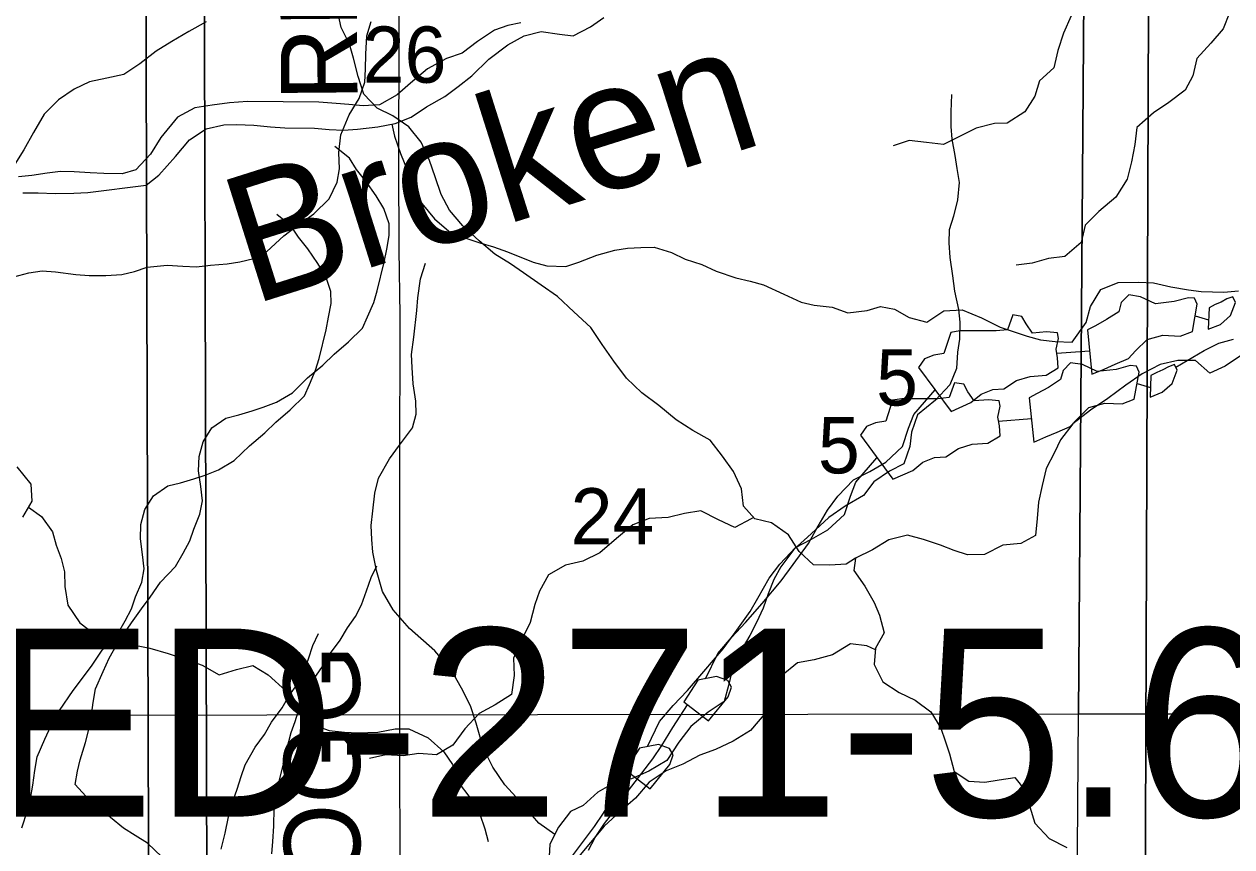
# Model space of a CAD drawing. Extents: x -21.1 to 50.3, y 0 to 22.1.
# Drawn here: x 3.669 to 4.567, y 18.044 to 18.656 of the extents above; entities that cross this region are included whole.
import ezdxf

# ---------------------------------------------------------------- set-up
doc = ezdxf.new("R2010")
doc.units = 0
for name, color, linetype in [('GM_X_Minor_Lake', 7, 'Continuous'), ('GM_X_Minor_River', 7, 'Continuous'), ('GM_X_Minor_River_Text', 7, 'Continuous'), ('GM_X_Section', 7, 'Continuous'), ('GM_X_Section_Text', 7, 'Continuous'), ('GM_X_Township_Road', 7, 'Continuous'), ('GM_X_Township_Road_Text', 7, 'Continuous'), ('SH_Data', 7, 'Continuous')]:
    doc.layers.add(name, color=color, linetype=linetype)

msp = doc.modelspace()

# ---------------------------------------------------------------- linework, layer by layer
at = {"layer": 'GM_X_Minor_Lake'}
for points in [[(4.46292, 18.3955), (4.47198, 18.39939), (4.48028, 18.4029), (4.49009, 18.40718), (4.49534, 18.41293), (4.50397, 18.42137), (4.51569, 18.42453), (4.52859, 18.42391), (4.53765, 18.42742), (4.54122, 18.44757), (4.53927, 18.4521), (4.53472, 18.45243), (4.52413, 18.44966), (4.51012, 18.44799), (4.49906, 18.45319), (4.49032, 18.45461), (4.4847, 18.44886), (4.48288, 18.44201), (4.47384, 18.43622), (4.46555, 18.43158), (4.45952, 18.42848)], [(4.54939, 18.42906), (4.55845, 18.43257), (4.56596, 18.43911), (4.56965, 18.44901), (4.5677, 18.45316), (4.56317, 18.4516), (4.55902, 18.44927), (4.55449, 18.44733), (4.54997, 18.445)], [(4.54997, 18.445), (4.54939, 18.42906)], [(4.35818, 18.36782), (4.3729, 18.37443), (4.38041, 18.38058), (4.3891, 18.38409), (4.39743, 18.38456), (4.40685, 18.39073), (4.41705, 18.39387), (4.4288, 18.39476), (4.43784, 18.40017), (4.43737, 18.40775), (4.43616, 18.41419), (4.43797, 18.42217), (4.43716, 18.42634), (4.42919, 18.42701), (4.41858, 18.42614), (4.41396, 18.43292), (4.41086, 18.43858), (4.40402, 18.43965), (4.39997, 18.4286), (4.39164, 18.42775), (4.36471, 18.42784), (4.3579, 18.42663), (4.35276, 18.41102), (4.34519, 18.4098), (4.3384, 18.40707), (4.33392, 18.40057)], [(4.45952, 18.42848), (4.46292, 18.3955)], [(4.33392, 18.40057), (4.35818, 18.36782)], [(4.41963, 18.34499), (4.42869, 18.34888), (4.43699, 18.35238), (4.44681, 18.35666), (4.45205, 18.36241), (4.46068, 18.37085), (4.4724, 18.37401), (4.4853, 18.37339), (4.49436, 18.3769), (4.49793, 18.39705), (4.49598, 18.40158), (4.49143, 18.40191), (4.48084, 18.39915), (4.46683, 18.39748), (4.45577, 18.40267), (4.44703, 18.40409), (4.44141, 18.39834), (4.43959, 18.39149), (4.43055, 18.3857), (4.42226, 18.38106), (4.41623, 18.37796)], [(4.5061, 18.37855), (4.51516, 18.38206), (4.52267, 18.38859), (4.52636, 18.3985), (4.52441, 18.40265), (4.51988, 18.40108), (4.51573, 18.39876), (4.5112, 18.39681), (4.50668, 18.39449)], [(4.50668, 18.39449), (4.5061, 18.37855)], [(4.31489, 18.3173), (4.32961, 18.32391), (4.33712, 18.33006), (4.34581, 18.33357), (4.35414, 18.33404), (4.36356, 18.34021), (4.37376, 18.34336), (4.38551, 18.34424), (4.39455, 18.34965), (4.39408, 18.35723), (4.39288, 18.36367), (4.39468, 18.37166), (4.39388, 18.37582), (4.3859, 18.3765), (4.37529, 18.37563), (4.37067, 18.3824), (4.36757, 18.38807), (4.36073, 18.38913), (4.35668, 18.37808), (4.34835, 18.37723), (4.32142, 18.37732), (4.31461, 18.37611), (4.30948, 18.3605), (4.30191, 18.35928), (4.29511, 18.35655), (4.29063, 18.35005)], [(4.41623, 18.37796), (4.41963, 18.34499)], [(4.29063, 18.35005), (4.31489, 18.3173)], [(4.17759, 18.13746), (4.19218, 18.15545), (4.19475, 18.16268), (4.19204, 18.16759), (4.18367, 18.17053), (4.16967, 18.16773), (4.15923, 18.15168)], [(4.15923, 18.15168), (4.17759, 18.13746)], [(4.1343, 18.08694), (4.14889, 18.10493), (4.15146, 18.11217), (4.14875, 18.11707), (4.14038, 18.12002), (4.12638, 18.11721), (4.11594, 18.10116)], [(4.11594, 18.10116), (4.1343, 18.08694)]]:
    msp.add_lwpolyline(points, dxfattribs=at)
at = {"layer": 'GM_X_Minor_River'}
for points in [[(3.6677, 18.53063), (3.67909, 18.53052), (3.69161, 18.53001), (3.70566, 18.53025), (3.71591, 18.5309), (3.75924, 18.53616), (3.76881, 18.54366), (3.7811, 18.55759), (3.79148, 18.57002), (3.80409, 18.57825), (3.81702, 18.58116), (3.82652, 18.58144), (3.83942, 18.58094), (3.85193, 18.57967), (3.86255, 18.5788), (3.88457, 18.57858), (3.89557, 18.57771), (3.90619, 18.57722), (3.91645, 18.57788), (3.93165, 18.57962), (3.94458, 18.58215), (3.9564, 18.58697), (3.96786, 18.59445), (3.98161, 18.60229), (3.99156, 18.60978), (4.00151, 18.61766), (4.01416, 18.63007), (4.02831, 18.64056), (4.04053, 18.64727), (4.05309, 18.65057), (4.06674, 18.64853), (4.07697, 18.64728), (4.08995, 18.65399), (4.09989, 18.66111)], [(4.28702, 18.25864), (4.28018, 18.25407), (4.26801, 18.25329), (4.25583, 18.25366), (4.24516, 18.26353), (4.23715, 18.27607), (4.22458, 18.2848), (4.21202, 18.28783), (4.20364, 18.29732), (4.2021, 18.31025), (4.19637, 18.32318), (4.18798, 18.33457), (4.17883, 18.34635), (4.16589, 18.35356), (4.1537, 18.36153), (4.14075, 18.37217), (4.12817, 18.38165), (4.11674, 18.39267), (4.10721, 18.40521), (4.09844, 18.41775), (4.09005, 18.43028), (4.07748, 18.44206), (4.06529, 18.45345), (4.0531, 18.4618), (4.04015, 18.47092), (4.03025, 18.47775), (4.01882, 18.48496), (4.00701, 18.49483), (3.99482, 18.50585), (3.98491, 18.51762), (3.9788, 18.5294), (3.97422, 18.54233), (3.97002, 18.55449), (3.96391, 18.56818), (3.95476, 18.57957), (3.94295, 18.58793), (3.93115, 18.59362), (3.92124, 18.60387), (3.91703, 18.61718), (3.91359, 18.63086), (3.91053, 18.64113), (3.90442, 18.65367), (3.90175, 18.66622)], [(4.44738, 18.66234), (4.4417, 18.6494), (4.43753, 18.63646), (4.4345, 18.62353), (4.42386, 18.61401), (4.42046, 18.6026), (4.41286, 18.5908), (4.39994, 18.58241), (4.39042, 18.58202), (4.37673, 18.57858), (4.3524, 18.56638), (4.33984, 18.56789), (4.3269, 18.56939), (4.31511, 18.56557)], [(4.56534, 18.66439), (4.5604, 18.65259), (4.55129, 18.64193), (4.54103, 18.63051), (4.53801, 18.61757), (4.53232, 18.60692), (4.52015, 18.59778), (4.50875, 18.59016), (4.49621, 18.57911), (4.49471, 18.56656), (4.49244, 18.55363), (4.48903, 18.54069), (4.48068, 18.52737), (4.46814, 18.51671), (4.45788, 18.50643), (4.45486, 18.49349), (4.4427, 18.48321), (4.43052, 18.48167), (4.41835, 18.47824), (4.40656, 18.4767)], [(3.80397, 18.65773), (3.79104, 18.65049), (3.7785, 18.64325), (3.76671, 18.636), (3.75455, 18.62648), (3.74277, 18.61848), (3.73021, 18.6158), (3.71728, 18.61313), (3.70587, 18.60779), (3.69409, 18.59979), (3.68345, 18.58912), (3.67548, 18.57542), (3.66827, 18.56248), (3.6603, 18.54992), (3.64928, 18.53812), (3.63674, 18.52593)], [(3.66081, 18.46789), (3.67218, 18.47092), (3.68204, 18.47244), (3.69189, 18.47168), (3.70705, 18.46979), (3.71691, 18.46903), (3.72942, 18.46903), (3.74117, 18.46979), (3.75065, 18.47207), (3.76013, 18.47511), (3.77491, 18.47662), (3.78666, 18.47587), (3.7969, 18.47549), (3.80713, 18.47663), (3.81964, 18.47777), (3.82912, 18.47929), (3.83935, 18.48156), (3.84921, 18.48687), (3.86173, 18.49863), (3.87121, 18.50584), (3.8841, 18.51494), (3.89548, 18.52595), (3.90155, 18.53846), (3.90307, 18.54832), (3.9027, 18.56046), (3.90422, 18.57373), (3.91029, 18.58853), (3.91788, 18.60067), (3.92206, 18.6128), (3.92244, 18.62266), (3.92283, 18.63366), (3.92359, 18.64732), (3.92663, 18.65794)], [(4.03798, 18.65718), (4.02846, 18.65499), (4.01856, 18.65168), (4.00594, 18.64306), (3.99446, 18.63444), (3.98266, 18.63039), (3.96853, 18.62293), (3.9559, 18.61204), (3.94594, 18.60341), (3.93295, 18.59594), (3.9208, 18.59531), (3.91018, 18.59617), (3.9007, 18.59703), (3.8878, 18.59792), (3.83466, 18.59846), (3.82137, 18.59745), (3.80844, 18.59568), (3.79552, 18.59391), (3.78254, 18.58683), (3.77024, 18.57176), (3.76252, 18.5593), (3.75177, 18.54764), (3.74149, 18.5447), (3.72782, 18.54484), (3.71758, 18.54532), (3.70582, 18.5462), (3.69557, 18.5463), (3.68569, 18.54526), (3.67429, 18.54348), (3.66441, 18.54244)], [(4.35835, 18.60375), (4.35797, 18.59086), (4.35796, 18.57986), (4.35871, 18.57038), (4.36098, 18.55824), (4.36249, 18.54876), (4.364, 18.53814), (4.36286, 18.52524), (4.35982, 18.51311), (4.35678, 18.50287), (4.3564, 18.49338), (4.35715, 18.48239), (4.35904, 18.46873), (4.36055, 18.45736), (4.36358, 18.4437), (4.36471, 18.43422), (4.36432, 18.4217), (4.3628, 18.41184), (4.36204, 18.39971), (4.3571, 18.38757), (4.34648, 18.37619), (4.33321, 18.36519), (4.32865, 18.35229), (4.32751, 18.34167), (4.32295, 18.32878), (4.31234, 18.32347), (4.30058, 18.3155), (4.293, 18.30526), (4.27935, 18.29729), (4.26721, 18.28895), (4.25394, 18.27681), (4.24104, 18.26505), (4.23156, 18.25215), (4.22625, 18.24267), (4.22207, 18.23205), (4.21828, 18.22143), (4.21334, 18.21081), (4.20841, 18.20095), (4.20272, 18.19147), (4.19589, 18.17857), (4.19247, 18.16378), (4.18943, 18.15202), (4.1773, 18.14406), (4.1644, 18.13344), (4.15568, 18.12168), (4.14658, 18.10802), (4.1333, 18.10005), (4.12041, 18.09437), (4.10752, 18.09133), (4.09539, 18.0845), (4.08439, 18.07464), (4.07491, 18.07009), (4.06619, 18.05833), (4.05974, 18.04581), (4.05897, 18.03216)], [(3.94207, 18.58166), (3.9441, 18.57266), (3.94852, 18.5597), (3.95408, 18.54635), (3.95926, 18.53338), (3.96447, 18.52269), (3.97384, 18.5112), (3.98625, 18.50044), (3.99723, 18.49691), (4.00744, 18.49339), (4.01766, 18.49024), (4.02825, 18.48672), (4.04715, 18.47893), (4.05737, 18.47617), (4.07141, 18.47565), (4.08131, 18.47896), (4.09465, 18.48415), (4.10798, 18.48781), (4.11748, 18.48923), (4.12736, 18.48989), (4.13723, 18.49017), (4.15009, 18.48624), (4.16029, 18.4812), (4.17278, 18.47728), (4.18336, 18.47223), (4.19811, 18.46715), (4.20871, 18.46476), (4.21855, 18.462), (4.23367, 18.45501), (4.24651, 18.44918), (4.25636, 18.4468), (4.26963, 18.44553), (4.28135, 18.44123), (4.2958, 18.44298), (4.3057, 18.44592), (4.31592, 18.44392), (4.32687, 18.43773), (4.34012, 18.43418), (4.35274, 18.44279), (4.36641, 18.44341), (4.38077, 18.43757), (4.39474, 18.43059), (4.40496, 18.42706), (4.4148, 18.42393), (4.42464, 18.42117), (4.43563, 18.41992), (4.44815, 18.41941), (4.45856, 18.43412), (4.46171, 18.44586), (4.46944, 18.4587), (4.4824, 18.46389), (4.49758, 18.46411), (4.50859, 18.46362), (4.52146, 18.46045), (4.53473, 18.45842), (4.5442, 18.45718), (4.5609, 18.45663), (4.57192, 18.45766)], [(3.77107, 18.03628), (3.76036, 18.04648), (3.75119, 18.05212), (3.7424, 18.05777), (3.73284, 18.0657), (3.7229, 18.07362), (3.71448, 18.08155), (3.70644, 18.09024), (3.70829, 18.10013), (3.71014, 18.10849), (3.71426, 18.12143), (3.71649, 18.13018), (3.71834, 18.14007), (3.7198, 18.15109), (3.72165, 18.16136), (3.72728, 18.17431), (3.73179, 18.18421), (3.7382, 18.19564), (3.7484, 18.21051), (3.75595, 18.22081), (3.76237, 18.22958), (3.76992, 18.24064), (3.78127, 18.25248), (3.78693, 18.26239), (3.79183, 18.27153), (3.79482, 18.28029), (3.79933, 18.29133), (3.80117, 18.30122), (3.79997, 18.31185), (3.79838, 18.32361), (3.7987, 18.33425), (3.80169, 18.34528), (3.8081, 18.35558), (3.81872, 18.36285), (3.82822, 18.36518), (3.8381, 18.36828), (3.84646, 18.37098), (3.85633, 18.37484), (3.8681, 18.38174), (3.87945, 18.39282), (3.89082, 18.40238), (3.89915, 18.4104), (3.90975, 18.41958), (3.92035, 18.42989), (3.92411, 18.43827), (3.92862, 18.44893), (3.93124, 18.45769), (3.93644, 18.47899), (3.93829, 18.48849), (3.94014, 18.49876), (3.94009, 18.5075), (3.93622, 18.51887), (3.93046, 18.52834), (3.92278, 18.53931), (3.91588, 18.54801), (3.91051, 18.55633), (3.8998, 18.56501)], [(3.66685, 18.05798), (3.67097, 18.07092), (3.6732, 18.07967), (3.67505, 18.08955), (3.67651, 18.10058), (3.67836, 18.11084), (3.68399, 18.12379), (3.68851, 18.13369), (3.69491, 18.14513), (3.70511, 18.16), (3.71266, 18.17029), (3.71908, 18.17907), (3.72663, 18.19013), (3.73799, 18.20197), (3.74364, 18.21187), (3.74854, 18.22102), (3.75153, 18.22977), (3.75604, 18.24081), (3.75788, 18.2507), (3.75668, 18.26133), (3.7551, 18.2731), (3.75542, 18.28373), (3.7584, 18.29477), (3.76481, 18.30506), (3.77543, 18.31233), (3.78493, 18.31467), (3.79481, 18.31776), (3.80317, 18.32047), (3.81304, 18.32432), (3.82481, 18.33122), (3.83616, 18.3423), (3.84753, 18.35186), (3.85586, 18.35989), (3.86646, 18.36906), (3.87706, 18.37938), (3.88082, 18.38775), (3.88533, 18.39842), (3.88795, 18.40717), (3.89315, 18.42847), (3.895, 18.43798), (3.89685, 18.44824), (3.8968, 18.45698), (3.89293, 18.46836), (3.88717, 18.47782), (3.87949, 18.48879), (3.87259, 18.49749), (3.86722, 18.50582), (3.85651, 18.5145)], [(4.06342, 18.05295), (4.05141, 18.06136), (4.03739, 18.07767), (4.02603, 18.0898), (4.01731, 18.10308), (4.01239, 18.11294), (4.00785, 18.12545), (4.00482, 18.13569), (4.00066, 18.14859), (3.99384, 18.16186), (3.98627, 18.17551), (3.97415, 18.18954), (3.9552, 18.20623), (3.94308, 18.22026), (3.93513, 18.23391), (3.93058, 18.24946), (3.92794, 18.26312), (3.92719, 18.2726), (3.92681, 18.28284), (3.92796, 18.29384), (3.92948, 18.30711), (3.93214, 18.31811), (3.94048, 18.33252), (3.94769, 18.34276), (3.95755, 18.35566), (3.96021, 18.3659), (3.95984, 18.37538), (3.95795, 18.38828), (3.9572, 18.40042), (3.95683, 18.41028), (3.95835, 18.42317), (3.96063, 18.44289), (3.96139, 18.45238), (3.9633, 18.46641), (3.96709, 18.47817)], [(4.53971, 18.43907), (4.54965, 18.4361)], [(4.5253, 18.40075), (4.54629, 18.41313), (4.55723, 18.41856), (4.56819, 18.42171)], [(4.57408, 18.4096), (4.56191, 18.4016), (4.5505, 18.39626), (4.53984, 18.40575), (4.5269, 18.40574), (4.51359, 18.40267), (4.50028, 18.39581), (4.48812, 18.38743), (4.47482, 18.37753), (4.46189, 18.36877), (4.44859, 18.35848), (4.43947, 18.34668), (4.43492, 18.33717), (4.42885, 18.32537), (4.42583, 18.31282), (4.42318, 18.30026), (4.42206, 18.28809), (4.42093, 18.27554), (4.40991, 18.26944), (4.39659, 18.26828), (4.3829, 18.26142), (4.37035, 18.26103), (4.36045, 18.26444), (4.35017, 18.26823), (4.33761, 18.27239), (4.32581, 18.2758), (4.31174, 18.27236), (4.29957, 18.26474), (4.28702, 18.25864)], [(4.43673, 18.41119), (4.46111, 18.41304)], [(4.17553, 18.1689), (4.18461, 18.18762), (4.19472, 18.19949), (4.20521, 18.21061), (4.21757, 18.22478), (4.23179, 18.24163), (4.24076, 18.25386), (4.25196, 18.26954), (4.25754, 18.27947), (4.26609, 18.29436), (4.27394, 18.30469), (4.28556, 18.31695), (4.29762, 18.32315), (4.30968, 18.33011), (4.32207, 18.34163), (4.32647, 18.35534), (4.33052, 18.36563), (4.34626, 18.38391)], [(4.49642, 18.38855), (4.50636, 18.38559)], [(4.39344, 18.36067), (4.41782, 18.36252)], [(4.13224, 18.11839), (4.14132, 18.1371), (4.15143, 18.14897), (4.16192, 18.16009), (4.17428, 18.17426), (4.1885, 18.19111), (4.19747, 18.20335), (4.20867, 18.21903), (4.21425, 18.22895), (4.2228, 18.24384), (4.23065, 18.25417), (4.24227, 18.26644), (4.25433, 18.27264), (4.26639, 18.2796), (4.27878, 18.29111), (4.28318, 18.30482), (4.28723, 18.31511), (4.30298, 18.33339)], [(3.66749, 18.28905), (3.67445, 18.30113), (3.67382, 18.31367), (3.66333, 18.32669)], [(3.67182, 18.29656), (3.68154, 18.28966), (3.68978, 18.27818), (3.69233, 18.26828), (3.69603, 18.25837), (3.69858, 18.24847), (3.69885, 18.23745), (3.70098, 18.22375), (3.70996, 18.21036), (3.72239, 18.20112), (3.73411, 18.19645), (3.74851, 18.1944), (3.76215, 18.1916), (3.77577, 18.18767), (3.78864, 18.18336), (3.80112, 18.17905), (3.81357, 18.17171), (3.82652, 18.17576), (3.8387, 18.17868), (3.85001, 18.17172), (3.86317, 18.15981), (3.87065, 18.14872), (3.88152, 18.13532), (3.89552, 18.13024), (3.90689, 18.12898), (3.91676, 18.1285), (3.93157, 18.12911), (3.9445, 18.13164), (3.95475, 18.13154), (3.9691, 18.12494), (3.98077, 18.11456), (3.98712, 18.105), (3.99079, 18.09281), (4.0009, 18.07941), (4.00761, 18.06795), (4.0113, 18.05727), (4.01386, 18.04775)], [(4.21112, 18.28885), (4.20936, 18.28782), (4.19719, 18.28135), (4.18501, 18.28703), (4.17206, 18.29386), (4.15989, 18.29195), (4.14772, 18.28889), (4.13364, 18.28811), (4.12147, 18.28353), (4.10931, 18.27325), (4.09677, 18.26258), (4.08422, 18.25648), (4.07129, 18.25342), (4.05874, 18.24618), (4.05191, 18.23401), (4.0485, 18.22411), (4.0451, 18.2108), (4.03865, 18.19748), (4.03258, 18.18416), (4.03298, 18.17123), (4.0311, 18.15716), (4.01893, 18.14954), (4.00715, 18.14306), (3.99651, 18.13164), (3.98739, 18.11946), (3.97523, 18.11222), (3.96229, 18.11334), (3.9505, 18.11142), (3.93756, 18.11217), (3.92539, 18.10949)], [(4.28702, 18.25864), (4.28589, 18.24951), (4.2939, 18.23773), (4.30077, 18.22557), (4.30497, 18.21607), (4.30841, 18.20314), (4.30196, 18.19173), (4.30084, 18.17956), (4.30732, 18.16664), (4.31951, 18.15867), (4.33132, 18.15297), (4.34312, 18.14424), (4.35037, 18.13208), (4.35381, 18.12258), (4.35687, 18.11308), (4.36031, 18.09977), (4.37136, 18.09256), (4.38315, 18.09182), (4.3938, 18.09373), (4.4056, 18.09527), (4.41322, 18.08577), (4.41666, 18.0736), (4.42049, 18.06144), (4.43116, 18.05005), (4.4441, 18.04322)], [(3.8529, 18.03863), (3.85361, 18.04775), (3.85431, 18.05915), (3.85461, 18.07245), (3.8557, 18.08195), (3.85831, 18.0926), (3.86128, 18.1044), (3.86388, 18.11657), (3.86724, 18.12874), (3.87023, 18.13712), (3.87323, 18.14663), (3.87622, 18.15538), (3.88376, 18.16834), (3.89056, 18.17788), (3.89584, 18.18702), (3.90377, 18.1977), (3.90905, 18.20685), (3.91509, 18.21524), (3.91961, 18.224), (3.92336, 18.23428), (3.92673, 18.24417), (3.93087, 18.25293)], [(3.81502, 18.04209), (3.81799, 18.05388), (3.82059, 18.06605), (3.82395, 18.07823), (3.82695, 18.0866), (3.82994, 18.09611), (3.83293, 18.10487), (3.84047, 18.11782), (3.84727, 18.12736), (3.85255, 18.1365), (3.86048, 18.14719), (3.86576, 18.15633), (3.8718, 18.16472), (3.87632, 18.17349), (3.88007, 18.18376), (3.88344, 18.19366), (3.88758, 18.20242)], [(4.30185, 18.19049), (4.29549, 18.19324), (4.28331, 18.19475), (4.27001, 18.18674), (4.25631, 18.18292), (4.24376, 18.18063), (4.2316, 18.17072), (4.22781, 18.15741), (4.22022, 18.14371), (4.20883, 18.13038), (4.1959, 18.12238), (4.18297, 18.11628), (4.17119, 18.11208), (4.15864, 18.10522), (4.14609, 18.10026), (4.13355, 18.09188), (4.12329, 18.08008), (4.11189, 18.07018), (4.10011, 18.05914), (4.0796, 18.03477)], [(4.08841, 18.04126), (4.09323, 18.0508), (4.10033, 18.06112), (4.10892, 18.07221), (4.11825, 18.08559), (4.12797, 18.0986), (4.13619, 18.10931), (4.14291, 18.11925), (4.1511, 18.13262), (4.16212, 18.14944)], [(4.07496, 18.03508), (4.08468, 18.04808), (4.0929, 18.0588), (4.09962, 18.06873), (4.10781, 18.0821), (4.11883, 18.09892)]]:
    msp.add_lwpolyline(points, dxfattribs=at)
at = {"layer": 'GM_X_Section'}
for points in [[(3.45029, 19.15441), (4.46024, 19.14326), (4.45293, 18.14262), (3.44648, 18.14125)], [(4.46024, 19.14326), (5.46172, 19.1492), (5.45742, 18.14589), (4.45293, 18.14262)], [(2.75941, 19.00342), (3.80166, 19.0044), (3.80452, 18.01477), (2.7666, 18.00853)], [(3.83539, 19.00471), (4.83075, 19.0046), (4.83425, 17.98542), (3.80452, 18.01477), (3.80166, 19.0044)], [(5.47114, 18.99721), (5.48815, 17.97251), (4.50247, 17.98887), (4.50596, 18.94006), (4.50668, 19.00183)], [(2.71612, 18.9529), (3.75837, 18.95389), (3.76124, 17.96425), (2.72331, 17.95801)], [(3.7921, 18.95419), (4.78746, 18.95409), (4.79096, 17.9349), (3.76124, 17.96425), (3.75837, 18.95389)], [(4.50596, 18.94006), (4.50247, 17.98887), (4.50289, 17.92975), (3.48086, 17.90781), (3.48506, 18.92038)], [(4.45293, 18.14262), (5.45742, 18.14589), (5.45266, 17.13084), (4.44556, 17.13365)]]:
    msp.add_lwpolyline(points, close=True, dxfattribs=at)
at = {"layer": 'GM_X_Township_Road'}
msp.add_lwpolyline([(3.94848, 17.77344), (3.9484, 17.82506), (3.94806, 18.3195), (3.94822, 18.4394), (3.94758, 18.488), (3.94727, 18.5529), (3.94791, 18.74202), (3.94774, 18.79957), (3.94743, 18.84034), (3.94727, 18.86719), (3.94694, 18.91148), (3.9471, 18.95256), (3.94694, 18.96711), (3.94663, 18.99588), (3.94651, 19.01379), (3.9463, 19.03394), (3.9461, 19.06211), (3.94589, 19.08134), (3.94548, 19.12094)], dxfattribs=at)

# ---------------------------------------------------------------- texts
at = {"layer": 'GM_X_Minor_River_Text'}
msp.add_text('Broken', height=0.094723, rotation=17.56941, dxfattribs=at).set_placement((3.8381, 18.44685))
at = {"layer": 'GM_X_Section_Text'}
for s, height, p in [('26', 0.041856, (3.92045, 18.61248)), ('5', 0.04186, (4.30235, 18.37224)), ('5', 0.04186, (4.25906, 18.32172)), ('24', 0.041856, (4.07512, 18.2688))]:
    msp.add_text(s, height=height, rotation=0.00001, dxfattribs=at).set_placement(p)
at = {"layer": 'GM_X_Township_Road_Text'}
for s, rotation, p in [('RD', 90.49365, (3.91663, 18.59911)), ('KELLOGG', 90.14628, (3.91912, 17.83091))]:
    msp.add_text(s, height=0.056818, rotation=rotation, dxfattribs=at).set_placement(p)
at = {"layer": 'SH_Data'}
msp.add_text('MED-271-5.64', height=0.14, dxfattribs=at).set_placement((3.48439, 18.06624))

doc.saveas('drawing.dxf')
